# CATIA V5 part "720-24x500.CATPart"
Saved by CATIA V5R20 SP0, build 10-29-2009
Part number: 720-24x500
Definition: NONE
Nomenclature: 720-24x500
Source: Unknown
Description: 720-24x500
Bounding box of the stored display mesh (mm): x 0 to 500, y -12 to 12, z -12 to 12
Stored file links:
  C:\Users\Utente\Desktop\IO LAVORO\3D X SITO CF\X SITO\720\720-24x500.CATPart
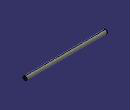
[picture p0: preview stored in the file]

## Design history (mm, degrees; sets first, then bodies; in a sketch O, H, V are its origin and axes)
Body1 "720-24x500" (main body)
  Solid1: solid without history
